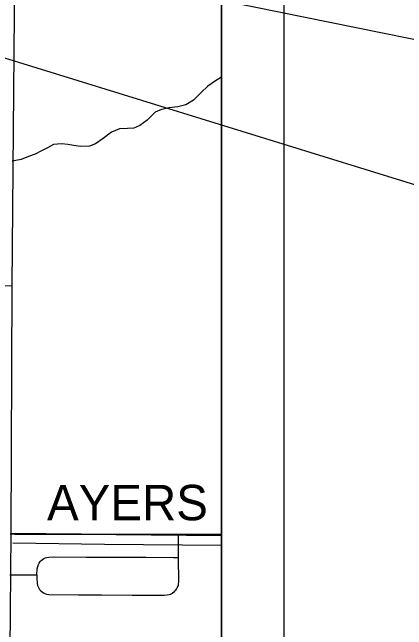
# Model space of a CAD drawing. Extents: x 0 to 34, y 0 to 22.
# Drawn here: x 8.565 to 9.197, y 18.272 to 19.262 of the extents above; entities that cross this region are included whole.
import ezdxf

# ---------------------------------------------------------------- set-up
doc = ezdxf.new("R2010")
doc.units = 0
for name, color, linetype in [('GM_X_Corporation', 7, 'Continuous'), ('GM_X_Minor_River', 7, 'Continuous'), ('GM_X_Township_Road', 7, 'Continuous'), ('GM_X_Township_Road_Text', 7, 'Continuous'), ('SH_Data', 7, 'Continuous'), ('SH_Text', 7, 'Continuous')]:
    doc.layers.add(name, color=color, linetype=linetype)

msp = doc.modelspace()

# ---------------------------------------------------------------- linework, layer by layer
at = {"layer": 'GM_X_Corporation'}
for points in [[(2.1, 14.1), (8.9, 14.1), (8.9, 20.9), (5.89055, 20.9)], [(8.9, 14.37894), (8.9, 20.9)]]:
    msp.add_lwpolyline(points, dxfattribs=at)
for points in [[(7.54127, 19.86087), (8.56945, 19.85372), (8.56962, 19.44742), (8.56457, 18.82324), (7.52848, 18.83427)], [(8.9, 18.42344), (8.9, 19.44053), (8.56962, 19.44742), (8.56457, 18.82324), (8.56257, 18.42645)], [(8.9, 17.41639), (8.9, 18.42344), (8.56257, 18.42645), (8.55788, 17.86518), (8.55531, 17.77577), (8.50493, 17.42275)]]:
    msp.add_lwpolyline(points, close=True, dxfattribs=at)
at = {"layer": 'GM_X_Minor_River'}
for points in [[(8.9, 19.15807), (8.89063, 19.15259), (8.87843, 19.14363), (8.8681, 19.13389), (8.85547, 19.12115), (8.84328, 19.11371), (8.8304, 19.11084), (8.8164, 19.10912), (8.80428, 19.10661), (8.79401, 19.10181), (8.78101, 19.08945), (8.76956, 19.08048), (8.75968, 19.07643), (8.74948, 19.0758), (8.73663, 19.07558), (8.72409, 19.07005), (8.71074, 19.05997), (8.69854, 19.05139), (8.68866, 19.04734), (8.67393, 19.04715), (8.66375, 19.04879), (8.65394, 19.05005), (8.64376, 19.05132), (8.63127, 19.04996), (8.62177, 19.04514), (8.61188, 19.03996), (8.60161, 19.03477), (8.59136, 19.03073), (8.57921, 19.02632), (8.56482, 19.02347)], [(8.9, 18.40739), (8.71285, 18.40901), (8.56593, 18.41085)]]:
    msp.add_lwpolyline(points, dxfattribs=at)
at = {"layer": 'GM_X_Township_Road'}
msp.add_line((8.83087, 18.4253), (8.83109, 18.388), dxfattribs=at)
for points in [[(8.56154, 18.42562), (8.56929, 18.42559), (8.60099, 18.42549), (8.65696, 18.42547), (8.70486, 18.42549), (8.74839, 18.42531), (8.77388, 18.4253), (8.83087, 18.4253)], [(8.83087, 18.4253), (8.85536, 18.42524), (8.87899, 18.4252), (8.9, 18.42517)], [(8.60468, 18.36007), (8.60509, 18.36988), (8.60594, 18.37368), (8.60698, 18.37672), (8.60814, 18.37906), (8.60959, 18.38123), (8.6113, 18.38321), (8.6133, 18.38492), (8.61553, 18.3863), (8.6179, 18.38739), (8.62042, 18.38813), (8.62363, 18.38854), (8.63053, 18.38881), (8.68342, 18.38864), (8.72636, 18.38856), (8.75311, 18.38843), (8.77924, 18.38825), (8.82343, 18.38804), (8.83109, 18.388)], [(8.83109, 18.388), (8.83134, 18.34895), (8.83104, 18.34548), (8.83061, 18.34326), (8.83, 18.3414), (8.82929, 18.33988), (8.82851, 18.33845), (8.82773, 18.33727), (8.82669, 18.33577), (8.82545, 18.33421), (8.82363, 18.33245), (8.82161, 18.33082)], [(8.56137, 18.36006), (8.56968, 18.36006), (8.58217, 18.36006), (8.60468, 18.36007)], [(8.60468, 18.36007), (8.60459, 18.35423), (8.60517, 18.34695), (8.60575, 18.34326), (8.60645, 18.34088), (8.60748, 18.33863), (8.60883, 18.33653), (8.61087, 18.3342), (8.61277, 18.3326), (8.61486, 18.33126), (8.61712, 18.33023), (8.6201, 18.32936), (8.62378, 18.32876), (8.67098, 18.328), (8.70827, 18.32782), (8.75735, 18.32757), (8.79591, 18.32737), (8.80835, 18.32747), (8.81328, 18.32784), (8.81631, 18.32844), (8.81865, 18.32926), (8.82018, 18.32991), (8.82161, 18.33082)]]:
    msp.add_lwpolyline(points, dxfattribs=at)
at = {"layer": 'SH_Data'}
for p, q in [((9, 21), (9, 14)), ((9, 21), (9, 14)), ((8.9, 20.9), (8.9, 14.1)), ((8.9, 20.9), (8.9, 14.1))]:
    msp.add_line(p, q, dxfattribs=at)
at = {"layer": 'SH_Text'}
msp.add_lwpolyline([(7.02792, 19.66119), (9.32697, 18.94981), (9.32697, 19.19461)], close=True, dxfattribs=at)

# ---------------------------------------------------------------- texts
at = {"layer": 'GM_X_Township_Road_Text'}
msp.add_text('AYERS', height=0.056818, rotation=0.00001, dxfattribs=at).set_placement((8.62082, 18.44759))

doc.saveas('drawing.dxf')
